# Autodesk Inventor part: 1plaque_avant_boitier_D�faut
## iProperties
Created: 2011-01
Part Number: 1plaque_avant_boitier_D�faut
Document SubType Name: Modeling
Designer: eric
Density: 1 g/cm^3
Mass: 5.23283 g
Surface Area: 40.173 cm^2
Volume: 5.23283 cm^3
Author: eric
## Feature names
1. Base1
